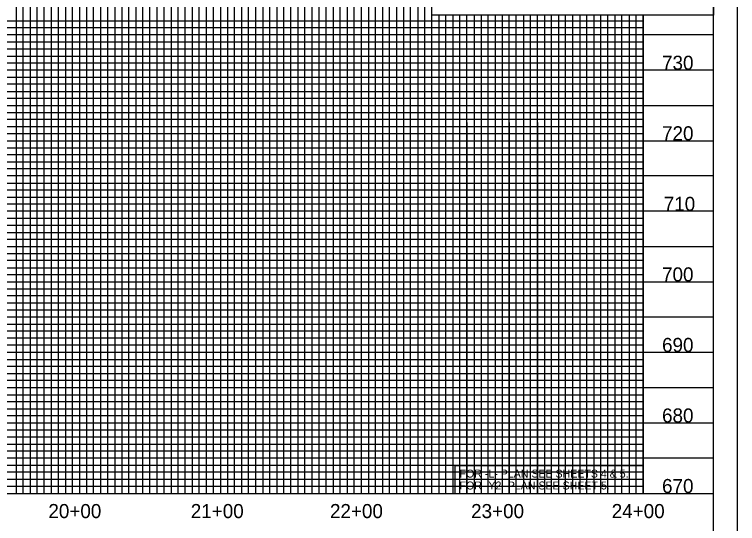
# Model space of a CAD drawing. Extents: x 1524869 to 1526553, y 501099 to 502199.
# Drawn here: x 1526040 to 1526553, y 501652 to 502013 of the extents above; entities that cross this region are included whole.
import ezdxf

# ---------------------------------------------------------------- set-up
doc = ezdxf.new("R2010")
doc.units = 0
for name, color, linetype in [('Exist Vertical Profile Horizontal Axis Label Major', 7, 'Continuous'), ('Exist Vertical Profile Vertical Axis Label', 7, 'Continuous'), ('Prop Grid Mask', 7, 'Continuous'), ('Prop Horizontal Alignment Curve and Spiral Data', 7, 'Continuous'), ('Sheet Layout Profile Border Port 1', 7, 'Continuous'), ('Sheet Plot Border Outside CELL', 7, 'Continuous'), ('Sheet Profile CELL', 7, 'Continuous'), ('Sheet Profile Grid Major CELL', 7, 'Continuous'), ('Sheet Profile Grid Middle CELL', 7, 'Continuous'), ('Sheet Profile Grid Minor CELL', 7, 'Continuous'), ('Sheet Sticker Exception Certification CELL', 7, 'Continuous')]:
    doc.layers.add(name, color=color, linetype=linetype)

msp = doc.modelspace()

# ---------------------------------------------------------------- linework, layer by layer
at = {"layer": 'Prop Grid Mask'}
msp.add_lwpolyline([(1526352.41, 501673.56), (1526486.08, 501673.56), (1526486.08, 501693.19), (1526352.41, 501693.19)], close=True, dxfattribs=at)
at = {"layer": 'Sheet Layout Profile Border Port 1'}
msp.add_lwpolyline([(1525086.08, 502173.56), (1525058.64, 501673.56), (1526486.08, 501673.56), (1526486.08, 502012.51), (1526336.03, 502012.51), (1526336.08, 502173.56)], close=True, dxfattribs=at)
msp.add_lwpolyline([(1525086.08, 502173.56), (1525058.64, 501673.56), (1526486.08, 501673.56), (1526486.08, 502012.51), (1526336.03, 502012.51), (1526336.08, 502173.56)], close=True, dxfattribs=at)
at = {"layer": 'Sheet Plot Border Outside CELL'}
msp.add_lwpolyline([(1524869.08, 501098.56), (1526553.08, 501098.56), (1526553.08, 502198.56), (1524869.08, 502198.56)], close=True, dxfattribs=at)
at = {"layer": 'Sheet Profile CELL'}
msp.add_line((1525036.08, 501673.56), (1526536.08, 501673.56), dxfattribs=at)
msp.add_lwpolyline([(1526536.08, 502173.56), (1525036.08, 502173.56), (1525036.08, 501123.56), (1526536.08, 501123.56)], close=True, dxfattribs=at)
at = {"layer": 'Sheet Profile Grid Major CELL'}
for points in [[(1526036.08, 502173.56), (1526086.08, 502173.56), (1526086.08, 501673.56), (1526136.08, 501673.56), (1526136.08, 502173.56), (1526186.08, 502173.56), (1526186.08, 501673.56), (1526236.08, 501673.56), (1526236.08, 502159.84)], [(1526286.08, 502159.84), (1526286.08, 501673.56), (1526336.08, 501673.56), (1526336.08, 502173.56), (1526362.38, 502173.56)], [(1526486.08, 502012.51), (1526486.08, 501673.56), (1526536.08, 501673.56), (1526536.08, 502023.56)], [(1526386.08, 502012.51), (1526386.08, 501673.56), (1526436.08, 501673.56), (1526436.08, 501673.56), (1526436.08, 502012.51)], [(1526536.08, 501973.56), (1525036.08, 501973.56), (1525036.08, 501923.56), (1526536.08, 501923.56)], [(1526536.08, 501873.56), (1525036.08, 501873.56), (1525036.08, 501823.56), (1526536.08, 501823.56)], [(1526536.08, 501773.56), (1525036.08, 501773.56), (1525036.08, 501773.56), (1525036.08, 501723.56), (1526536.08, 501723.56)]]:
    msp.add_lwpolyline(points, dxfattribs=at)
at = {"layer": 'Sheet Profile Grid Middle CELL'}
for points in [[(1526011.08, 501673.56), (1526061.08, 501673.56), (1526061.08, 502173.56), (1526111.08, 502173.56), (1526111.08, 501673.56), (1526161.08, 501673.56), (1526161.08, 502173.56), (1526211.08, 502173.56)], [(1526211.08, 502159.84), (1526211.08, 501673.56), (1526261.08, 501673.56), (1526261.08, 502159.84)], [(1526311.08, 502159.84), (1526311.08, 501673.56), (1526361.08, 501673.56), (1526361.08, 502012.51)], [(1526361.08, 501936.36), (1526361.08, 501673.56), (1526411.08, 501673.56), (1526411.08, 502012.51)], [(1526411.08, 501936.36), (1526411.08, 501673.56), (1526461.08, 501673.56), (1526461.08, 502012.51)], [(1526536.08, 501998.56), (1525036.08, 501998.56), (1525036.08, 501948.56), (1526361.08, 501948.56)], [(1526361.08, 501948.56), (1526536.08, 501948.56)], [(1526536.08, 501898.56), (1525036.08, 501898.56), (1525036.08, 501848.56), (1526536.08, 501848.56)], [(1526536.08, 501798.56), (1525036.08, 501798.56), (1525036.08, 501748.56), (1526536.08, 501748.56)], [(1526536.08, 501698.56), (1525036.08, 501698.56)]]:
    msp.add_lwpolyline(points, dxfattribs=at)
at = {"layer": 'Sheet Profile Grid Minor CELL'}
for p, q in [((1525086.08, 502008.56), (1526486.08, 502008.56)), ((1526486.08, 501988.56), (1525086.08, 501988.56)), ((1525086.08, 501983.56), (1526486.08, 501983.56)), ((1526486.08, 501963.56), (1525086.08, 501963.56)), ((1525086.08, 501958.56), (1526486.08, 501958.56)), ((1526486.08, 501938.56), (1525086.08, 501938.56)), ((1525086.08, 501933.56), (1526486.08, 501933.56)), ((1526486.08, 501928.56), (1525086.08, 501928.56)), ((1525086.08, 501918.56), (1526486.08, 501918.56)), ((1526486.08, 501913.56), (1525086.08, 501913.56)), ((1525086.08, 501908.56), (1526486.08, 501908.56)), ((1526486.08, 501903.56), (1525086.08, 501903.56)), ((1525086.08, 501893.56), (1526486.08, 501893.56)), ((1526486.08, 501888.56), (1525086.08, 501888.56)), ((1525086.08, 501883.56), (1526486.08, 501883.56)), ((1526486.08, 501878.56), (1525086.08, 501878.56)), ((1525086.08, 501868.56), (1526486.08, 501868.56)), ((1526486.08, 501863.56), (1525086.08, 501863.56)), ((1525086.08, 501858.56), (1526486.08, 501858.56)), ((1526486.08, 501853.56), (1525086.08, 501853.56)), ((1525086.08, 501843.56), (1526486.08, 501843.56)), ((1526486.08, 501838.56), (1525086.08, 501838.56)), ((1525086.08, 501833.56), (1526486.08, 501833.56)), ((1526486.08, 501828.56), (1525086.08, 501828.56)), ((1525086.08, 501818.56), (1526486.08, 501818.56)), ((1526486.08, 501813.56), (1525086.08, 501813.56)), ((1525086.08, 501808.56), (1526486.08, 501808.56)), ((1526486.08, 501803.56), (1525086.08, 501803.56)), ((1525086.08, 501793.56), (1526486.08, 501793.56)), ((1526486.08, 501788.56), (1525086.08, 501788.56)), ((1526486.08, 501783.56), (1525086.08, 501783.56)), ((1526486.08, 501778.56), (1525086.08, 501778.56)), ((1525086.08, 501768.56), (1526486.08, 501768.56)), ((1526486.08, 501763.56), (1525086.08, 501763.56)), ((1525086.08, 501758.56), (1526486.08, 501758.56)), ((1526486.08, 501753.56), (1525086.08, 501753.56)), ((1525086.08, 501743.56), (1526486.08, 501743.56)), ((1526486.08, 501738.56), (1525086.08, 501738.56)), ((1525086.08, 501733.56), (1526486.08, 501733.56)), ((1526486.08, 501728.56), (1525086.08, 501728.56)), ((1525086.08, 501718.56), (1526486.08, 501718.56)), ((1526486.08, 501713.56), (1525086.08, 501713.56)), ((1525086.08, 501708.56), (1526486.08, 501708.56)), ((1526486.08, 501703.56), (1525086.08, 501703.56)), ((1525086.08, 501693.56), (1526486.08, 501693.56)), ((1526486.08, 501688.56), (1525086.08, 501688.56)), ((1525086.08, 501683.56), (1526486.08, 501683.56))]:
    msp.add_line(p, q, dxfattribs=at)
for points in [[(1526041.08, 502173.56), (1526041.08, 501673.56), (1526046.08, 501673.56), (1526046.08, 502173.56)], [(1526051.08, 502173.56), (1526051.08, 501673.56), (1526056.08, 501673.56), (1526056.08, 502173.56)], [(1526066.08, 502173.56), (1526066.08, 501673.56), (1526071.08, 501673.56), (1526071.08, 502173.56)], [(1526076.08, 502173.56), (1526076.08, 501673.56), (1526081.08, 501673.56), (1526081.08, 502173.56)], [(1526091.08, 502173.56), (1526091.08, 501673.56), (1526096.08, 501673.56), (1526096.08, 502173.56)], [(1526101.08, 502173.56), (1526101.08, 501673.56), (1526106.08, 501673.56), (1526106.08, 502173.56)], [(1526116.08, 502173.56), (1526116.08, 501673.56), (1526121.08, 501673.56), (1526121.08, 502173.56)], [(1526126.08, 502173.56), (1526126.08, 501673.56), (1526131.08, 501673.56), (1526131.08, 502173.56)], [(1526141.08, 502173.56), (1526141.08, 501673.56), (1526146.08, 501673.56), (1526146.08, 502173.56)], [(1526151.08, 502173.56), (1526151.08, 501673.56), (1526156.08, 501673.56), (1526156.08, 502173.56)], [(1526166.08, 502173.56), (1526166.08, 501673.56), (1526171.08, 501673.56), (1526171.08, 502173.56)], [(1526176.08, 502173.56), (1526176.08, 501673.56), (1526181.08, 501673.56), (1526181.08, 502173.56)], [(1526191.08, 502159.84), (1526191.08, 501673.56), (1526196.08, 501673.56), (1526196.08, 502159.84)], [(1526201.08, 502159.84), (1526201.08, 501673.56), (1526206.08, 501673.56), (1526206.08, 502159.84)], [(1526216.08, 502159.84), (1526216.08, 501673.56), (1526221.08, 501673.56), (1526221.08, 502159.84)], [(1526226.08, 501673.56), (1526231.08, 501673.56), (1526231.08, 502159.84)], [(1526226.08, 502159.84), (1526226.08, 501673.56)], [(1526241.08, 502159.84), (1526241.08, 501673.56), (1526246.08, 501673.56), (1526246.08, 502159.84)], [(1526251.08, 502159.84), (1526251.08, 501673.56), (1526256.08, 501673.56), (1526256.08, 502159.84)], [(1526266.08, 502159.84), (1526266.08, 501673.56), (1526271.08, 501673.56), (1526271.08, 502159.84)], [(1526276.08, 502159.84), (1526276.08, 501673.56), (1526281.08, 501673.56), (1526281.08, 502159.84)], [(1526291.08, 502159.84), (1526291.08, 501673.56), (1526296.08, 501673.56), (1526296.08, 502159.84)], [(1526301.08, 502159.84), (1526301.08, 501673.56), (1526306.08, 501673.56), (1526306.08, 502159.84)], [(1526316.08, 502159.84), (1526316.08, 501673.56), (1526321.08, 501673.56), (1526321.08, 502159.84)], [(1526326.08, 502159.84), (1526326.08, 501673.56), (1526331.08, 501673.56), (1526331.08, 502159.84)], [(1526341.08, 502012.51), (1526341.08, 501673.56), (1526346.08, 501673.56), (1526346.08, 502012.51)], [(1526351.08, 502012.51), (1526351.08, 501673.56), (1526356.08, 501673.56), (1526356.08, 502012.51)], [(1526366.08, 502012.51), (1526366.08, 501673.56), (1526366.08, 501673.56), (1526371.08, 501673.56), (1526376.08, 501673.56), (1526376.08, 502012.51)], [(1526371.08, 502012.51), (1526371.08, 501673.56)], [(1526381.07, 502012.51), (1526380.98, 501673.61), (1526385.98, 501673.61), (1526391.08, 501673.56), (1526391.08, 502012.51)], [(1526391.08, 501936.36), (1526391.08, 501673.56), (1526396.08, 501673.56), (1526396.08, 502012.51)], [(1526401.08, 502012.51), (1526401.08, 501673.56), (1526406.08, 501673.56), (1526406.08, 502012.51)], [(1526416.08, 502012.51), (1526416.08, 501673.56), (1526421.08, 501673.56), (1526421.08, 502012.51)], [(1526426.08, 502012.51), (1526426.08, 501673.56), (1526431.08, 501673.56), (1526431.08, 502012.51)], [(1526441.08, 502012.51), (1526441.08, 501673.56), (1526446.08, 501673.56), (1526446.08, 502012.51)], [(1526451.08, 502012.51), (1526451.08, 501673.56), (1526456.08, 501673.56), (1526456.08, 502012.51)], [(1526466.08, 502012.51), (1526466.08, 501673.56), (1526471.08, 501673.56), (1526471.08, 502012.51)], [(1526476.08, 502012.51), (1526476.08, 501673.56), (1526481.08, 501673.56), (1526481.08, 502012.51)], [(1526486.08, 502003.56), (1525086.08, 502003.56), (1525086.08, 501993.56), (1526486.08, 501993.56)], [(1526486.08, 501978.56), (1525086.08, 501978.56), (1525086.08, 501968.56), (1526486.08, 501968.56)], [(1526486.08, 501953.56), (1525086.08, 501953.56), (1525086.08, 501943.56), (1526486.08, 501943.56)], [(1526486.08, 501678.56), (1525086.08, 501678.56)]]:
    msp.add_lwpolyline(points, dxfattribs=at)
at = {"layer": 'Sheet Sticker Exception Certification CELL'}
for p, q in [((1526336.03, 502012.51), (1526336.03, 502036.01)), ((1526336.03, 502012.51), (1526336.03, 502036.01)), ((1526536.07, 502036), (1526536.07, 502012.5)), ((1526536.07, 502036), (1526536.07, 502012.5)), ((1526536.07, 502012.51), (1526336.03, 502012.51)), ((1526536.07, 502012.51), (1526336.03, 502012.51))]:
    msp.add_line(p, q, dxfattribs=at)

# ---------------------------------------------------------------- texts
at = {"layer": 'Exist Vertical Profile Horizontal Axis Label Major'}
for s, p in [('20+00', (1526064.01, 501656.06)), ('21+00', (1526165.07, 501656.06)), ('22+00', (1526263.85, 501656.06)), ('23+00', (1526364.02, 501656.06)), ('24+00', (1526463.8, 501656.06))]:
    msp.add_text(s, height=10, dxfattribs=at).set_placement(p)
at = {"layer": 'Exist Vertical Profile Vertical Axis Label'}
for s, p in [('730', (1526499.51, 501973.81)), ('720', (1526499.51, 501923.81)), ('710', (1526500.71, 501873.81)), ('700', (1526499.51, 501823.81)), ('690', (1526499.51, 501773.81)), ('680', (1526499.51, 501723.81)), ('670', (1526499.51, 501673.81))]:
    msp.add_text(s, height=10, dxfattribs=at).set_placement(p)
at = {"layer": 'Prop Horizontal Alignment Curve and Spiral Data'}
for s, p in [('FOR -L- PLAN SEE SHEETS 4 & 5.', (1526355.79, 501684.81)), ('FOR -Y2- PLAN SEE SHEET 5.', (1526355.79, 501676.37))]:
    msp.add_text(s, height=5.625, rotation=360, dxfattribs=at).set_placement(p)

doc.saveas('drawing.dxf')
